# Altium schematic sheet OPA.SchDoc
size A4
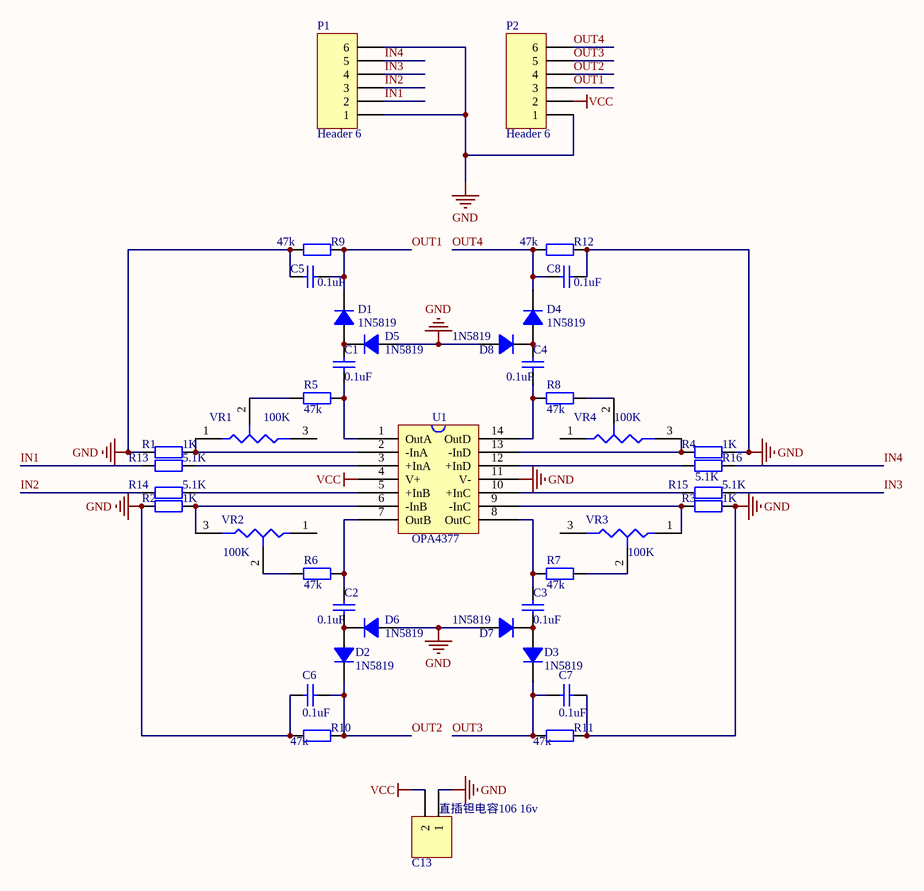
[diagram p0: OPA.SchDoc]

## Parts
C1  value 0.1uF  [0805]  (hidden comment: Cap)
C2  value 0.1uF  [0805]  (hidden comment: Cap)
C3  value 0.1uF  [0805]  (hidden comment: Cap)
C4  value 0.1uF  [0805]  (hidden comment: Cap)
C5  value 0.1uF  [0805]  (hidden comment: Cap)
C6  value 0.1uF  [0805]  (hidden comment: Cap)
C7  value 0.1uF  [0805]  (hidden comment: Cap)
C8  value 0.1uF  [0805]  (hidden comment: Cap)
C13  直插钽电容106 16v  [HDR1X2]
D1  1N5819  [SOD-123]
D2  1N5819  [SOD-123]
D3  1N5819  [SOD-123]
D4  1N5819  [SOD-123]
D5  1N5819  [SOD-123]
D6  1N5819  [SOD-123]
D7  1N5819  [SOD-123]
D8  1N5819  [SOD-123]
P1  Header 6  [HDR1X6]
P2  Header 6  [HDR1X6]
R1  value 1K  [0805]  (hidden comment: Res2)
R2  value 1K  [0805]  (hidden comment: Res2)
R3  value 1K  [0805]  (hidden comment: Res2)
R4  value 1K  [0805]  (hidden comment: Res2)
R5  value 47k  [0805]  (hidden comment: Res2)
R6  value 47k  [0805]  (hidden comment: Res2)
R7  value 47k  [0805]  (hidden comment: Res2)
R8  value 47k  [0805]  (hidden comment: Res2)
R9  value 47k  [0805]  (hidden comment: Res2)
R10  value 47k  [0805]  (hidden comment: Res2)
R11  value 47k  [0805]  (hidden comment: Res2)
R12  value 47k  [0805]  (hidden comment: Res2)
R13  value 5.1K  [0805]  (hidden comment: Res2)
R14  value 5.1K  [0805]  (hidden comment: Res2)
R15  value 5.1K  [0805]  (hidden comment: Res2)
R16  value 5.1K  [0805]  (hidden comment: Res2)
U1  OPA4377  [TSSOP14]
VR1  100K  [VR_small]
VR2  100K  [VR_small]
VR3  100K  [VR_small]
VR4  100K  [VR_small]

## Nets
GND: C5.1 C6.1 C7.2 C8.2 C13.1 D5.A D6.A D7.A D8.A P1.1 P1.6 P2.1 R1.1 R2.1 R3.2 R4.2 R9.1 R10.1 R11.2 R12.2 U1.11(V-)
VCC: C13.2 P2.2 U1.4(V+)
IN1: P1.2 R13.1
IN2: P1.3 R14.1
IN3: P1.4 R15.2
IN4: P1.5 R16.2
OUT1: C5.2 D1.K P2.3 R9.2
OUT2: C6.2 D2.K P2.4 R10.2
OUT3: C7.1 D3.K P2.5 R11.1
OUT4: C8.1 D4.K P2.6 R12.1
NetC1_1: C1.1 R5.2 U1.1(OutA)
NetC1_2: C1.2 D1.A D5.K
NetC2_1: C2.1 D2.A D6.K
NetC2_2: C2.2 R6.2 U1.7(OutB)
NetC3_1: C3.1 D3.A D7.K
NetC3_2: C3.2 R7.1 U1.8(OutC)
NetC4_1: C4.1 R8.1 U1.14(OutD)
NetC4_2: C4.2 D4.A D8.K
NetR1_2: R1.2 U1.2(-InA) VR1.1
NetR2_2: R2.2 U1.6(-InB) VR2.3
NetR3_1: R3.1 U1.9(-InC) VR3.1
NetR4_1: R4.1 U1.13(-InD) VR4.3
NetR5_1: R5.1 VR1.2
NetR6_1: R6.1 VR2.2
NetR7_2: R7.2 VR3.2
NetR8_2: R8.2 VR4.2
NetR13_2: R13.2 U1.3(+InA)
NetR14_2: R14.2 U1.5(+InB)
NetR15_1: R15.1 U1.10(+InC)
NetR16_1: R16.1 U1.12(+InD)

Not connected (* = marked no-connect by the designer): VR1 3; VR2 1; VR3 3; VR4 1

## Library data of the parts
C1-C8 = Cap: Capacitor
C13 = Header 2: Header, 2-Pin
D1-D8 = Diode SS16: 1N5819 二极管 Diode; Imax: 500mA
P1 P2 = Header 6: Header, 6-Pin
R1-R16 = Res2: Resistor
U1 = OPA4348: OPA4377 四路轨对轨运放
VR1-VR4 = LQ_VR1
